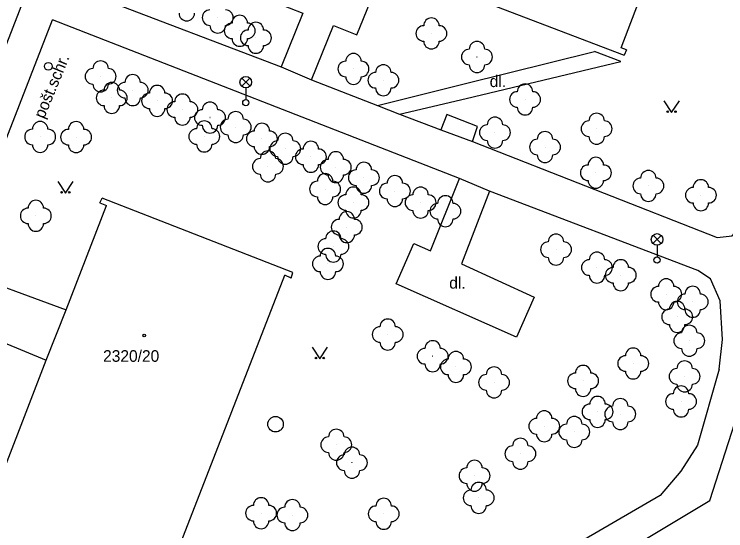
# Model space of a CAD drawing. Extents: x -737812 to -729375, y -1123000 to -1115500.
# Drawn here: x -736772.82 to -736726.91, y -1118537.52 to -1118504.18 of the extents above; entities that cross this region are included whole.
import ezdxf

# ---------------------------------------------------------------- set-up
doc = ezdxf.new("R2010")
doc.units = 0
for name, color, linetype in [('Doplněk polohopisu', 7, 'Continuous'), ('Doplňkové značky', 7, 'Continuous'), ('Komunikace', 7, 'Continuous'), ('Pomocné popisy', 7, 'Continuous'), ('Povr_ zn_ inž_ sítí - el_', 7, 'Continuous'), ('Povr_ zn_ inž_ sítí - kan_', 7, 'Continuous'), ('Stavební objekty', 7, 'Continuous'), ('Zeleň', 7, 'Continuous'), ('Značky druhů budov', 7, 'Continuous'), ('Značky druhů pozemků', 7, 'Continuous'), ('Čísla popisná', 7, 'Continuous')]:
    doc.layers.add(name, color=color, linetype=linetype)

msp = doc.modelspace()

# ---------------------------------------------------------------- linework, layer by layer
at = {"layer": 'Doplněk polohopisu'}
for p, q in [((-736769.48, -1118502.28), (-736755.6, -1118507.58)), ((-736776.61, -1118520.63), (-736770.36, -1118504.54)), ((-736744.09, -1118514.79), (-736770.36, -1118504.54)), ((-736755.6, -1118507.58), (-736753.63, -1118508.41)), ((-736753.63, -1118508.41), (-736749.38, -1118510.07)), ((-736749.38, -1118510.07), (-736747.95, -1118510.63)), ((-736747.95, -1118510.63), (-736745.3, -1118511.63)), ((-736745.3, -1118511.63), (-736743.25, -1118512.39)), ((-736743.25, -1118512.39), (-736727.47, -1118518.58)), ((-736742.15, -1118515.59), (-736744.09, -1118514.79)), ((-736728.7, -1118520.72), (-736742.15, -1118515.59)), ((-736727.88, -1118521.26), (-736728.7, -1118520.72)), ((-736727.26, -1118522.67), (-736727.88, -1118521.26)), ((-736727.12, -1118525.17), (-736727.26, -1118522.67)), ((-736727.34, -1118527.08), (-736727.12, -1118525.17)), ((-736727.34, -1118527.08), (-736728.72, -1118531.98)), ((-736728.72, -1118531.98), (-736729.81, -1118533.67)), ((-736729.81, -1118533.67), (-736731.14, -1118535.23)), ((-736731.14, -1118535.23), (-736738.89, -1118539.73))]:
    msp.add_line(p, q, dxfattribs=at)
for points in [[(-736753.63, -1118508.41), (-736752.22, -1118504.9), (-736750.71, -1118505.5), (-736749.61, -1118502.8), (-736757.5, -1118499.7), (-736758.6, -1118502.36), (-736754.19, -1118504.12), (-736755.6, -1118507.58)], [(-736749.38, -1118510.07), (-736743.79, -1118508.68), (-736735.37, -1118506.59)], [(-736747.95, -1118510.63), (-736743.66, -1118509.61), (-736733.67, -1118507.24), (-736735.37, -1118506.59)], [(-736743.25, -1118512.39), (-736742.92, -1118511.42), (-736744.91, -1118510.66), (-736745.3, -1118511.63)], [(-736742.15, -1118515.59), (-736743.96, -1118520.29), (-736739.28, -1118522.43), (-736740.41, -1118525.03), (-736748.17, -1118521.57), (-736747.04, -1118518.98), (-736745.97, -1118519.44), (-736744.09, -1118514.79)], [(-736727.47, -1118518.58), (-736726.5, -1118518.49), (-736725.87, -1118517.77), (-736725.85, -1118517.05)], [(-736776.61, -1118520.63), (-736769.48, -1118523.25)], [(-736777.77, -1118523.61), (-736770.77, -1118526.51)], [(-736743.89, -1118545.14), (-736727.94, -1118535.56), (-736725.53, -1118528.07)]]:
    msp.add_lwpolyline(points, dxfattribs=at)
at = {"layer": 'Doplňkové značky'}
for radius in [0.25, 0.0005]:
    msp.add_circle((-736770.62, -1118507.54), radius, dxfattribs=at)
at = {"layer": 'Komunikace'}
msp.add_lwpolyline([(-736747.14, -1118454.39), (-736748.27, -1118454.1), (-736749.26, -1118453.96), (-736750.31, -1118454.12), (-736751.31, -1118454.41), (-736752.15, -1118454.85), (-736753.35, -1118455.85), (-736753.98, -1118456.56), (-736754.48, -1118457.46), (-736756.85, -1118463.62), (-736757.26, -1118464.7), (-736766.16, -1118487.6), (-736792.53, -1118555.59), (-736793.01, -1118556.8), (-736794.94, -1118561.67), (-736795.2, -1118562.6), (-736795.31, -1118563.59), (-736795.29, -1118564.6), (-736795.18, -1118565.61), (-736794.91, -1118566.57), (-736794.52, -1118567.51), (-736794.05, -1118568.41), (-736793.89, -1118568.68)], dxfattribs=at)
at = {"layer": 'Povr_ zn_ inž_ sítí - el_'}
for p, q in [((-736758.144, -1118508.828), (-736757.616, -1118508.3)), ((-736757.608, -1118508.825), (-736758.136, -1118508.296)), ((-736757.88, -1118508.94), (-736757.88, -1118509.69)), ((-736731.604, -1118518.978), (-736731.076, -1118518.45)), ((-736731.068, -1118518.975), (-736731.596, -1118518.446)), ((-736731.34, -1118519.09), (-736731.34, -1118519.84))]:
    msp.add_line(p, q, dxfattribs=at)
for centre, radius in [((-736757.88, -1118508.565), 0.375), ((-736757.88, -1118509.89), 0.2), ((-736731.34, -1118518.715), 0.375), ((-736731.34, -1118520.04), 0.2)]:
    msp.add_circle(centre, radius, dxfattribs=at)
at = {"layer": 'Povr_ zn_ inž_ sítí - kan_'}
msp.add_circle((-736755.96, -1118530.64), 0.5, dxfattribs=at)
at = {"layer": 'Stavební objekty'}
msp.add_line((-736773.5, -1118567.74), (-736755.37, -1118521.02), dxfattribs=at)
for points in [[(-736733.66, -1118506.35), (-736731.11, -1118499.67), (-736729.88, -1118496.45), (-736725.99, -1118486.28), (-736724.72, -1118482.95), (-736723.5, -1118479.77)], [(-736743.58, -1118502.95), (-736733.46, -1118506.83)], [(-736733.32, -1118506.48), (-736733.66, -1118506.35)], [(-736733.32, -1118506.48), (-736733.46, -1118506.83)], [(-736767.29, -1118516.36), (-736767.15, -1118516.04)], [(-736754.85, -1118520.84), (-736767.15, -1118516.04)], [(-736767.29, -1118516.36), (-736766.86, -1118516.53)], [(-736769.48, -1118523.25), (-736766.86, -1118516.53)], [(-736754.96, -1118521.22), (-736755.37, -1118521.02)], [(-736754.96, -1118521.22), (-736754.85, -1118520.84)], [(-736770.77, -1118526.51), (-736769.48, -1118523.25)], [(-736774.71, -1118536.69), (-736770.77, -1118526.51)]]:
    msp.add_lwpolyline(points, dxfattribs=at)
at = {"layer": 'Zeleň'}
for centre in [(-736759.69, -1118504.4), (-736758.27, -1118505.25), (-736745.9, -1118505.42), (-736757.23, -1118505.7), (-736742.96, -1118506.94), (-736750.93, -1118507.71), (-736767.25, -1118508.19), (-736749, -1118508.44), (-736765.18, -1118509.08), (-736766.53, -1118509.58), (-736763.6, -1118509.77), (-736739.86, -1118509.68), (-736761.97, -1118510.33), (-736760.19, -1118510.85), (-736758.53, -1118511.46), (-736741.8, -1118511.82), (-736735.24, -1118511.57), (-736771.15, -1118512.1), (-736768.83, -1118512.11), (-736760.56, -1118512.07), (-736756.84, -1118512.22), (-736738.57, -1118512.75), (-736755.33, -1118512.86), (-736753.68, -1118513.38), (-736756.45, -1118514), (-736752.07, -1118514.05), (-736735.29, -1118514.41), (-736750.26, -1118514.73), (-736752.76, -1118515.46), (-736748.26, -1118515.59), (-736731.9, -1118515.26), (-736728.51, -1118515.86), (-736750.93, -1118516.33), (-736746.6, -1118516.34), (-736745, -1118516.89), (-736771.43, -1118517.19), (-736751.36, -1118517.92), (-736752.23, -1118519.17), (-736737.86, -1118519.37), (-736752.58, -1118520.29), (-736735.22, -1118520.53), (-736733.68, -1118521.02), (-736730.75, -1118522.25), (-736729.04, -1118522.74), (-736730.04, -1118523.71), (-736748.72, -1118524.85), (-736729.26, -1118525.25), (-736745.82, -1118526.25), (-736744.32, -1118526.94), (-736732.88, -1118526.72), (-736741.86, -1118527.94), (-736736.11, -1118527.84), (-736729.56, -1118527.55), (-736729.79, -1118529.17), (-736735.18, -1118529.84), (-736733.71, -1118529.98), (-736738.62, -1118530.77), (-736736.68, -1118531.14), (-736752.04, -1118531.96), (-736740.16, -1118532.54), (-736751.03, -1118533.12), (-736743.12, -1118533.96), (-736742.85, -1118535.39), (-736756.89, -1118536.38), (-736754.87, -1118536.5), (-736748.98, -1118536.42)]:
    msp.add_circle(centre, 0.0005, dxfattribs=at)
for centre, start, end in [((-736761.69, -1118504.11), 180, 360), ((-736760.19, -1118504.4), 90, 270), ((-736759.19, -1118504.4), 270, 90), ((-736758.27, -1118504.75), 360, 180), ((-736745.9, -1118504.92), 360, 180), ((-736759.69, -1118504.9), 180, 360), ((-736758.77, -1118505.25), 90, 270), ((-736757.77, -1118505.25), 270, 90), ((-736757.23, -1118505.2), 360, 180), ((-736746.4, -1118505.42), 90, 270), ((-736745.4, -1118505.42), 270, 90), ((-736757.73, -1118505.7), 90, 270), ((-736756.73, -1118505.7), 270, 90), ((-736758.27, -1118505.75), 180, 360), ((-736745.9, -1118505.92), 180, 360), ((-736742.96, -1118506.44), 360, 180), ((-736757.23, -1118506.2), 180, 360), ((-736750.93, -1118507.21), 360, 180), ((-736743.46, -1118506.94), 90, 270), ((-736742.46, -1118506.94), 270, 90), ((-736767.25, -1118507.69), 360, 180), ((-736751.43, -1118507.71), 90, 270), ((-736750.43, -1118507.71), 270, 90), ((-736767.75, -1118508.19), 90, 270), ((-736766.75, -1118508.19), 270, 90), ((-736749, -1118507.94), 360, 180), ((-736742.96, -1118507.44), 180, 360), ((-736765.18, -1118508.58), 360, 180), ((-736750.93, -1118508.21), 180, 360), ((-736749.5, -1118508.44), 90, 270), ((-736748.5, -1118508.44), 270, 90), ((-736767.25, -1118508.69), 180, 360), ((-736766.53, -1118509.08), 360, 180), ((-736765.68, -1118509.08), 90, 270), ((-736764.68, -1118509.08), 270, 90), ((-736739.86, -1118509.18), 360, 180), ((-736767.03, -1118509.58), 90, 270), ((-736766.03, -1118509.58), 270, 90), ((-736763.6, -1118509.27), 360, 180), ((-736749, -1118508.94), 180, 360), ((-736740.36, -1118509.68), 90, 270), ((-736739.36, -1118509.68), 270, 90), ((-736765.18, -1118509.58), 180, 360), ((-736764.1, -1118509.77), 90, 270), ((-736763.1, -1118509.77), 270, 90), ((-736761.97, -1118509.83), 360, 180), ((-736766.53, -1118510.08), 180, 360), ((-736762.47, -1118510.33), 90, 270), ((-736761.47, -1118510.33), 270, 90), ((-736760.19, -1118510.35), 360, 180), ((-736763.6, -1118510.27), 180, 360), ((-736760.69, -1118510.85), 90, 270), ((-736759.69, -1118510.85), 270, 90), ((-736758.53, -1118510.96), 360, 180), ((-736739.86, -1118510.18), 180, 360), ((-736761.97, -1118510.83), 180, 360), ((-736759.03, -1118511.46), 90, 270), ((-736758.03, -1118511.46), 270, 90), ((-736741.8, -1118511.32), 360, 180), ((-736735.24, -1118511.07), 360, 180), ((-736771.15, -1118511.6), 360, 180), ((-736768.83, -1118511.61), 360, 180), ((-736760.56, -1118511.57), 360, 180), ((-736760.19, -1118511.35), 180, 360), ((-736756.84, -1118511.72), 360, 180), ((-736742.3, -1118511.82), 90, 270), ((-736741.3, -1118511.82), 270, 90), ((-736735.74, -1118511.57), 90, 270), ((-736734.74, -1118511.57), 270, 90), ((-736771.65, -1118512.1), 90, 270), ((-736770.65, -1118512.1), 270, 90), ((-736769.33, -1118512.11), 90, 270), ((-736768.33, -1118512.11), 270, 90), ((-736761.06, -1118512.07), 90, 270), ((-736760.06, -1118512.07), 270, 90), ((-736757.34, -1118512.22), 90, 270), ((-736756.34, -1118512.22), 270, 90), ((-736755.33, -1118512.36), 360, 180), ((-736738.57, -1118512.25), 360, 180), ((-736758.53, -1118511.96), 180, 360), ((-736755.83, -1118512.86), 90, 270), ((-736754.83, -1118512.86), 270, 90), ((-736753.68, -1118512.88), 360, 180), ((-736741.8, -1118512.32), 180, 360), ((-736739.07, -1118512.75), 90, 270), ((-736738.07, -1118512.75), 270, 90), ((-736735.24, -1118512.07), 180, 360), ((-736771.15, -1118512.6), 180, 360), ((-736768.83, -1118512.61), 180, 360), ((-736760.56, -1118512.57), 180, 360), ((-736756.84, -1118512.72), 180, 360), ((-736756.45, -1118513.5), 360, 180), ((-736754.18, -1118513.38), 90, 270), ((-736753.18, -1118513.38), 270, 90), ((-736752.07, -1118513.55), 360, 180), ((-736738.57, -1118513.25), 180, 360), ((-736756.95, -1118514), 90, 270), ((-736755.95, -1118514), 270, 90), ((-736755.33, -1118513.36), 180, 360), ((-736752.57, -1118514.05), 90, 270), ((-736751.57, -1118514.05), 270, 90), ((-736750.26, -1118514.23), 360, 180), ((-736735.29, -1118513.91), 360, 180), ((-736753.68, -1118513.88), 180, 360), ((-736750.76, -1118514.73), 90, 270), ((-736749.76, -1118514.73), 270, 90), ((-736735.79, -1118514.41), 90, 270), ((-736734.79, -1118514.41), 270, 90), ((-736756.45, -1118514.5), 180, 360), ((-736752.76, -1118514.96), 360, 180), ((-736752.07, -1118514.55), 180, 360), ((-736748.26, -1118515.09), 360, 180), ((-736731.9, -1118514.76), 360, 180), ((-736753.26, -1118515.46), 90, 270), ((-736752.26, -1118515.46), 270, 90), ((-736748.76, -1118515.59), 90, 270), ((-736747.76, -1118515.59), 270, 90), ((-736735.29, -1118514.91), 180, 360), ((-736732.4, -1118515.26), 90, 270), ((-736731.4, -1118515.26), 270, 90), ((-736728.51, -1118515.36), 360, 180), ((-736750.93, -1118515.83), 360, 180), ((-736750.26, -1118515.23), 180, 360), ((-736746.6, -1118515.84), 360, 180), ((-736729.01, -1118515.86), 90, 270), ((-736728.01, -1118515.86), 270, 90), ((-736752.76, -1118515.96), 180, 360), ((-736751.43, -1118516.33), 90, 270), ((-736750.43, -1118516.33), 270, 90), ((-736747.1, -1118516.34), 90, 270), ((-736746.1, -1118516.34), 270, 90), ((-736745, -1118516.39), 360, 180), ((-736731.9, -1118515.76), 180, 360), ((-736771.43, -1118516.69), 360, 180), ((-736748.26, -1118516.09), 180, 360), ((-736745.5, -1118516.89), 90, 270), ((-736744.5, -1118516.89), 270, 90), ((-736728.51, -1118516.36), 180, 360), ((-736771.93, -1118517.19), 90, 270), ((-736770.93, -1118517.19), 270, 90), ((-736751.36, -1118517.42), 360, 180), ((-736750.93, -1118516.83), 180, 360), ((-736746.6, -1118516.84), 180, 360), ((-736751.86, -1118517.92), 90, 270), ((-736750.86, -1118517.92), 270, 90), ((-736745, -1118517.39), 180, 360), ((-736771.43, -1118517.69), 180, 360), ((-736752.23, -1118518.67), 360, 180), ((-736752.73, -1118519.17), 90, 270), ((-736751.36, -1118518.42), 180, 360), ((-736751.73, -1118519.17), 270, 90), ((-736737.86, -1118518.87), 360, 180), ((-736738.36, -1118519.37), 90, 270), ((-736737.36, -1118519.37), 270, 90), ((-736752.58, -1118519.79), 360, 180), ((-736752.23, -1118519.67), 180, 360), ((-736735.22, -1118520.03), 360, 180), ((-736753.08, -1118520.29), 90, 270), ((-736752.08, -1118520.29), 270, 90), ((-736737.86, -1118519.87), 180, 360), ((-736735.72, -1118520.53), 90, 270), ((-736734.72, -1118520.53), 270, 90), ((-736733.68, -1118520.52), 360, 180), ((-736734.18, -1118521.02), 90, 270), ((-736733.18, -1118521.02), 270, 90), ((-736752.58, -1118520.79), 180, 360), ((-736735.22, -1118521.03), 180, 360), ((-736733.68, -1118521.52), 180, 360), ((-736730.75, -1118521.75), 360, 180), ((-736731.25, -1118522.25), 90, 270), ((-736730.25, -1118522.25), 270, 90), ((-736729.04, -1118522.24), 360, 180), ((-736729.54, -1118522.74), 90, 270), ((-736728.54, -1118522.74), 270, 90), ((-736730.75, -1118522.75), 180, 360), ((-736730.04, -1118523.21), 360, 180), ((-736730.54, -1118523.71), 90, 270), ((-736729.54, -1118523.71), 270, 90), ((-736729.04, -1118523.24), 180, 360), ((-736748.72, -1118524.35), 360, 180), ((-736730.04, -1118524.21), 180, 360), ((-736729.26, -1118524.75), 360, 180), ((-736749.22, -1118524.85), 90, 270), ((-736748.22, -1118524.85), 270, 90), ((-736729.76, -1118525.25), 90, 270), ((-736728.76, -1118525.25), 270, 90), ((-736745.82, -1118525.75), 360, 180), ((-736748.72, -1118525.35), 180, 360), ((-736746.32, -1118526.25), 90, 270), ((-736745.32, -1118526.25), 270, 90), ((-736744.32, -1118526.44), 360, 180), ((-736732.88, -1118526.22), 360, 180), ((-736729.26, -1118525.75), 180, 360), ((-736744.82, -1118526.94), 90, 270), ((-736743.82, -1118526.94), 270, 90), ((-736733.38, -1118526.72), 90, 270), ((-736732.38, -1118526.72), 270, 90), ((-736729.56, -1118527.05), 360, 180), ((-736745.82, -1118526.75), 180, 360), ((-736741.86, -1118527.44), 360, 180), ((-736736.11, -1118527.34), 360, 180), ((-736730.06, -1118527.55), 90, 270), ((-736729.06, -1118527.55), 270, 90), ((-736744.32, -1118527.44), 180, 360), ((-736742.36, -1118527.94), 90, 270), ((-736741.36, -1118527.94), 270, 90), ((-736736.61, -1118527.84), 90, 270), ((-736735.61, -1118527.84), 270, 90), ((-736732.88, -1118527.22), 180, 360), ((-736741.86, -1118528.44), 180, 360), ((-736736.11, -1118528.34), 180, 360), ((-736729.79, -1118528.67), 360, 180), ((-736729.56, -1118528.05), 180, 360), ((-736735.18, -1118529.34), 360, 180), ((-736730.29, -1118529.17), 90, 270), ((-736729.29, -1118529.17), 270, 90), ((-736735.68, -1118529.84), 90, 270), ((-736734.68, -1118529.84), 270, 90), ((-736733.71, -1118529.48), 360, 180), ((-736738.62, -1118530.27), 360, 180), ((-736734.21, -1118529.98), 90, 270), ((-736733.21, -1118529.98), 270, 90), ((-736729.79, -1118529.67), 180, 360), ((-736739.12, -1118530.77), 90, 270), ((-736738.12, -1118530.77), 270, 90), ((-736736.68, -1118530.64), 360, 180), ((-736737.18, -1118531.14), 90, 270), ((-736736.18, -1118531.14), 270, 90), ((-736735.18, -1118530.34), 180, 360), ((-736733.71, -1118530.48), 180, 360), ((-736752.04, -1118531.46), 360, 180), ((-736752.54, -1118531.96), 90, 270), ((-736751.54, -1118531.96), 270, 90), ((-736740.16, -1118532.04), 360, 180), ((-736738.62, -1118531.27), 180, 360), ((-736736.68, -1118531.64), 180, 360), ((-736751.03, -1118532.62), 360, 180), ((-736740.66, -1118532.54), 90, 270), ((-736739.66, -1118532.54), 270, 90), ((-736752.04, -1118532.46), 180, 360), ((-736751.53, -1118533.12), 90, 270), ((-736750.53, -1118533.12), 270, 90), ((-736743.12, -1118533.46), 360, 180), ((-736740.16, -1118533.04), 180, 360), ((-736743.62, -1118533.96), 90, 270), ((-736742.62, -1118533.96), 270, 90), ((-736751.03, -1118533.62), 180, 360), ((-736742.85, -1118534.89), 360, 180), ((-736743.35, -1118535.39), 90, 270), ((-736743.12, -1118534.46), 180, 360), ((-736742.35, -1118535.39), 270, 90), ((-736756.89, -1118535.88), 360, 180), ((-736754.87, -1118536), 360, 180), ((-736748.98, -1118535.92), 360, 180), ((-736757.39, -1118536.38), 90, 270), ((-736756.39, -1118536.38), 270, 90), ((-736755.37, -1118536.5), 90, 270), ((-736754.37, -1118536.5), 270, 90), ((-736749.48, -1118536.42), 90, 270), ((-736748.48, -1118536.42), 270, 90), ((-736742.85, -1118535.89), 180, 360), ((-736756.89, -1118536.88), 180, 360), ((-736754.87, -1118537), 180, 360), ((-736748.98, -1118536.92), 180, 360)]:
    msp.add_arc(centre, 0.5, start, end, dxfattribs=at)
at = {"layer": 'Značky druhů budov'}
msp.add_circle((-736764.43, -1118524.91), 0.0875, dxfattribs=at)
at = {"layer": 'Značky druhů pozemků'}
for points in [[(-736730.9, -1118509.77), (-736730.4, -1118510.52), (-736729.9, -1118509.77)], [(-736770.02, -1118514.97), (-736769.52, -1118515.72), (-736769.02, -1118514.97)], [(-736753.6, -1118525.67), (-736753.1, -1118526.42), (-736752.6, -1118525.67)]]:
    msp.add_lwpolyline(points, dxfattribs=at)
for centre in [(-736730.65, -1118510.47), (-736730.15, -1118510.47), (-736769.77, -1118515.67), (-736769.27, -1118515.67), (-736753.35, -1118526.37), (-736752.85, -1118526.37)]:
    msp.add_circle(centre, 0.05, dxfattribs=at)

# ---------------------------------------------------------------- texts
at = {"layer": 'Pomocné popisy'}
msp.add_text('pošt.schr.', height=0.75, rotation=67.58, dxfattribs=at).set_placement((-736770.9, -1118510.97))
for p in [(-736742.14, -1118508.88), (-736744.75, -1118521.89)]:
    msp.add_text('dl.', height=0.75, dxfattribs=at).set_placement(p)
at = {"layer": 'Čísla popisná'}
msp.add_text('2320/20', height=0.75, dxfattribs=at).set_placement((-736767.09, -1118526.61))

doc.saveas('drawing.dxf')
